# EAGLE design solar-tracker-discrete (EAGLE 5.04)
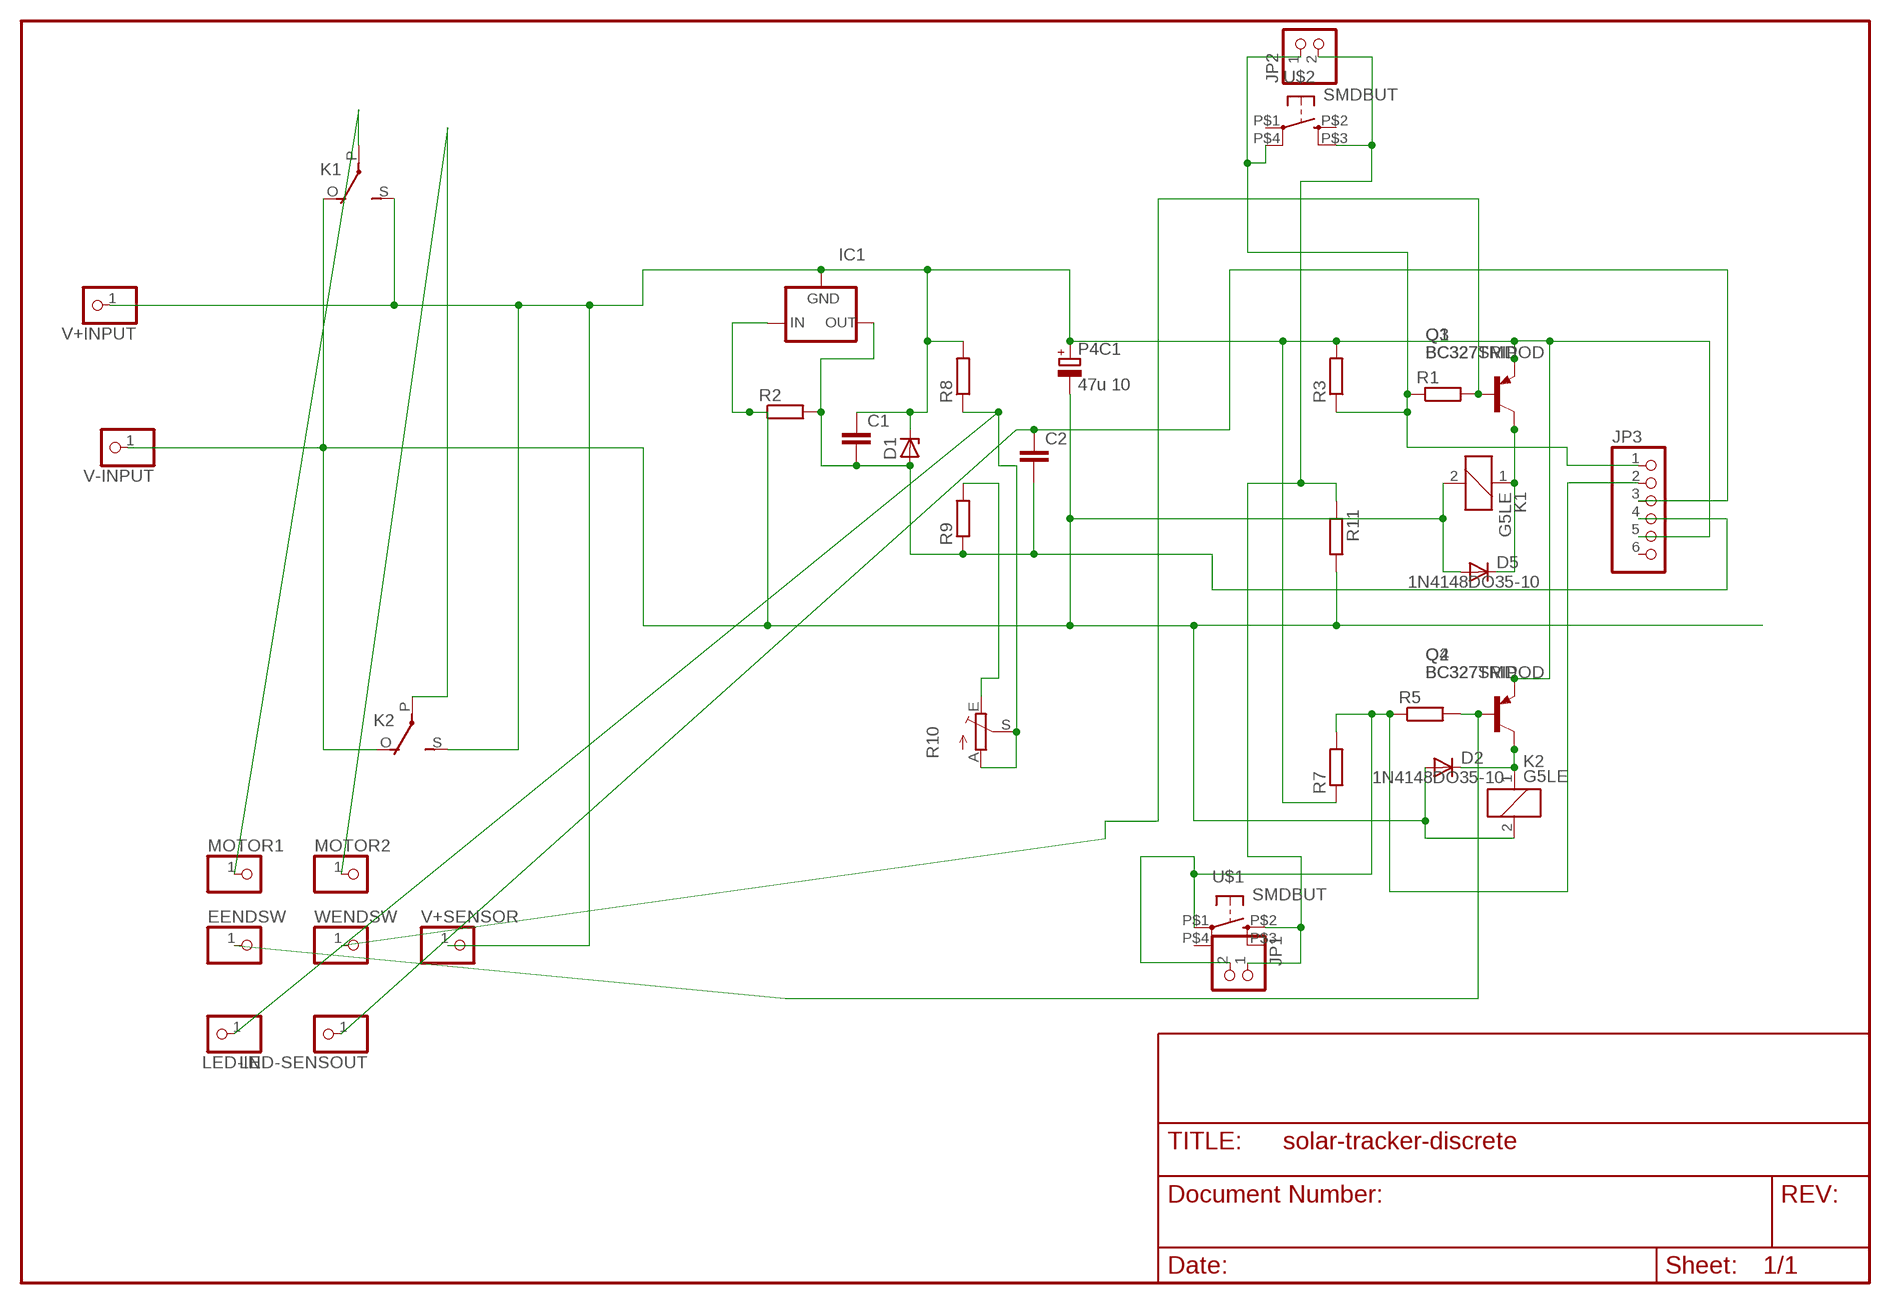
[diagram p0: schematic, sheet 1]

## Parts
C1  C-EUC1206  [C1206]
C2  C-EUC1206  [C1206]
D1  ZENER-DIODESOT23  [SOT23]
D2  1N4148DO35-10  [DO35-10]
D5  1N4148DO35-10  [DO35-10]
EENDSW  PINHD-1X1  [1X01]
IC1  79LXX  [79LXX]
JP1  PINHD-1X2  [1X02]
JP2  PINHD-1X2  [1X02]
JP3  PINHD-1X6  [1X06]
K1  G5LE  [G5LE]
K2  G5LE  [G5LE]
LED-IN  PINHD-1X1  [1X01]
LED-SENSOUT  PINHD-1X1  [1X01]
MOTOR1  PINHD-1X1  [1X01]
MOTOR2  PINHD-1X1  [1X01]
P4C1  47u 10  CPOL-EUE5-8.5  [E5-8,5]
Q1  BC327SMD  [SOT23-BEC]
Q2  BC327SMD  [SOT23-BEC]
Q3  BC327TRIPOD  [TO92]
Q4  BC327TRIPOD  [TO92]
R1  R-EU_0204/2V  [0204V]
R2  R-EU_0204/2V  [0204V]
R3  R-EU_0204/2V  [0204V]
R5  R-EU_0204/2V  [0204V]
R7  R-EU_0204/2V  [0204V]
R8  R-EU_0204/2V  [0204V]
R9  R-EU_0204/2V  [0204V]
R10  TRIM_EU-CA6V  [CA6V]
R11  R-EU_0204/2V  [0204V]
U$1  SMDBUT  [SMD10/5]
U$2  SMDBUT  [SMD10/5]
V+INPUT  PINHD-1X1  [1X01]
V+SENSOR  PINHD-1X1  [1X01]
V-INPUT  PINHD-1X1  [1X01]
WENDSW  PINHD-1X1  [1X01]

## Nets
MOTO1: K2.P(2:P) MOTOR2.1
MOTO2: K1.P(2:P) MOTOR1.1
N$1: R9.2 R10.E
N$3: LED-IN.1 R8.1 R10.A R10.S
N$5: C1.2 C2.2 D1.1(A) IC1.OUT JP3.4 R2.2 R9.1
N$6: JP1.1 JP2.2 R11.1 U$1.P$2(S) U$2.P$3(S1)
N$7: C2.1 JP3.3 LED-SENSOUT.1
N$8: Q1.B Q3.2(B) R1.2 WENDSW.1
N$11: D5.C K1.1 Q1.C Q3.3(C)
N$13: JP2.1 JP3.1 R1.1 R3.1 U$2.P$4(P1)
N$14: JP1.2 JP3.2 R5.1 R7.2 U$1.P$1(P)
N$15: EENDSW.1 Q2.B Q4.2(B) R5.2
Q1-C: D2.C K2.1 Q2.C Q4.3(C)
V+: C1.1 D1.3(C) IC1.GND JP3.5 K1.S(2:S) K2.S(2:S) P4C1.+ Q1.E Q2.E Q3.1(E) Q4.1(E) R3.2 R7.1 R8.2 V+INPUT.1 V+SENSOR.1
V-: D2.A D5.A IC1.IN K1.2 K1.O(2:O) K2.2 K2.O(2:O) P4C1.- R2.1 R11.2 V-INPUT.1
Unconnected: JP3.6 U$1.P$3(S1) U$1.P$4(P1) U$2.P$1(P) U$2.P$2(S)

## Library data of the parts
C1 C2 = rcl-2:C-EU: CAPACITOR, European symbol
D1 = diode-1:ZENER-DIODE: Z-Diode
D2 D5 = diode-1:1N4148: DIODE
EENDSW LED-IN LED-SENSOUT MOTOR1 MOTOR2 V+INPUT V+SENSOR V-INPUT WENDSW = pinhead(2):PINHD-1X1: PIN HEADER
IC1 = v-reg:79LXX: VOLTAGE REGULATOR
JP1 JP2 = pinhead:PINHD-1X2: PIN HEADER
JP3 = pinhead:PINHD-1X6: PIN HEADER
K1 K2 = relay:G5LE: RELAY 1 x switch, 10 A/120 V AC, 8 A/30 V DC, Omron
P4C1 = rcl:CPOL-EU: POLARIZED CAPACITOR, European symbol
Q1 Q2 = transistor-pnp:BC327*: PNP Transistror
Q3 Q4 = transistor-pnp:BC327: PNP Transistor
R1-R3 R5 R7-R9 R11 = rcl-2:R-EU_: RESISTOR, European symbol
R10 = pot:TRIM_EU-: POTENTIOMETER
U$1 U$2 = switch-omron:SMDBUT

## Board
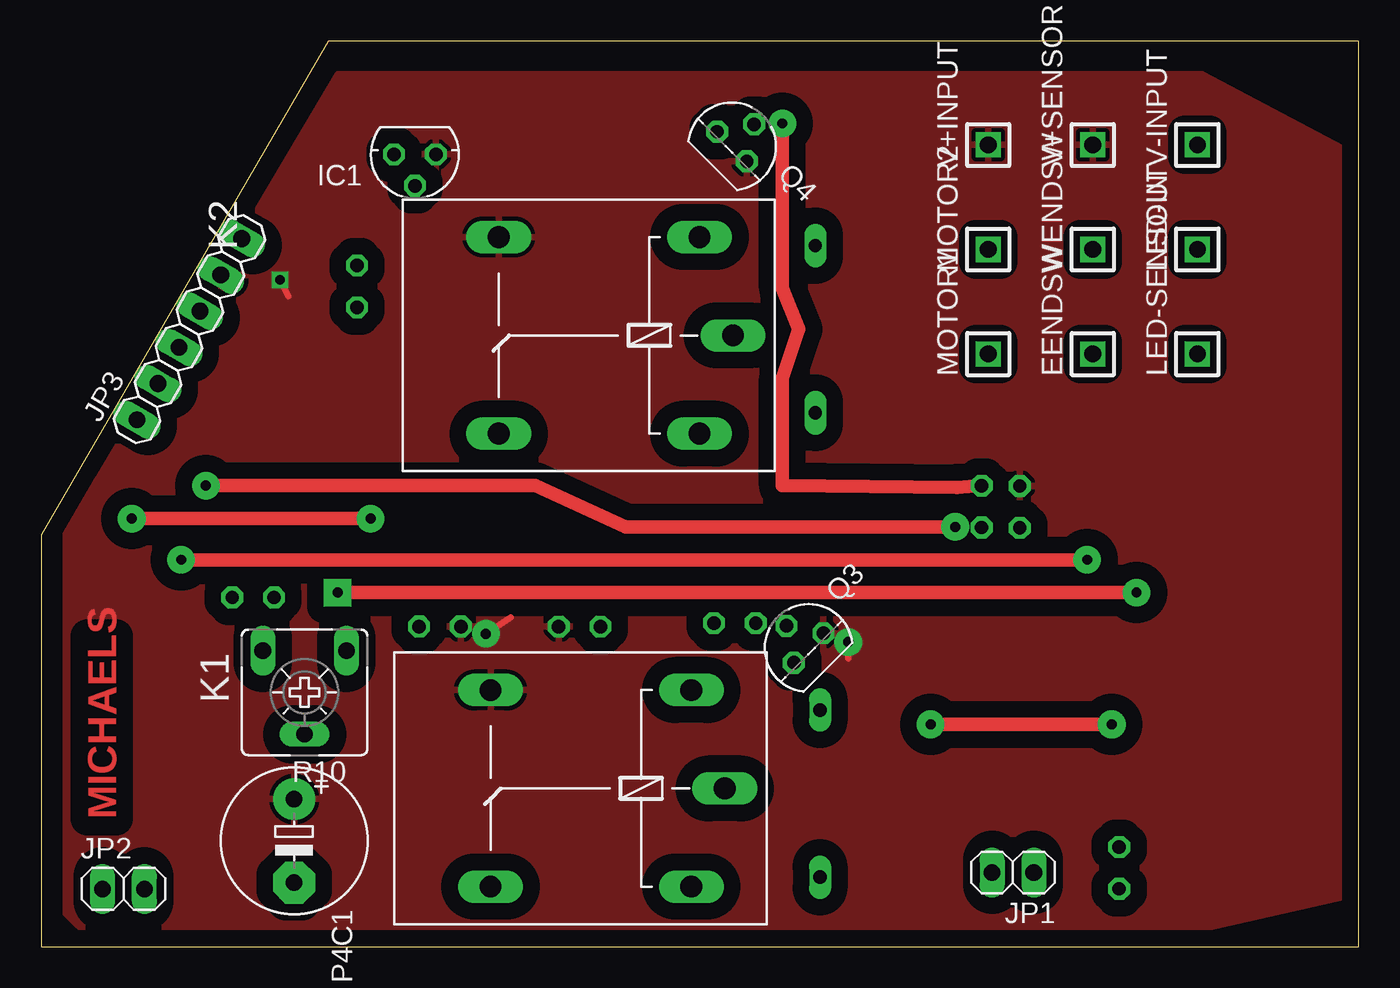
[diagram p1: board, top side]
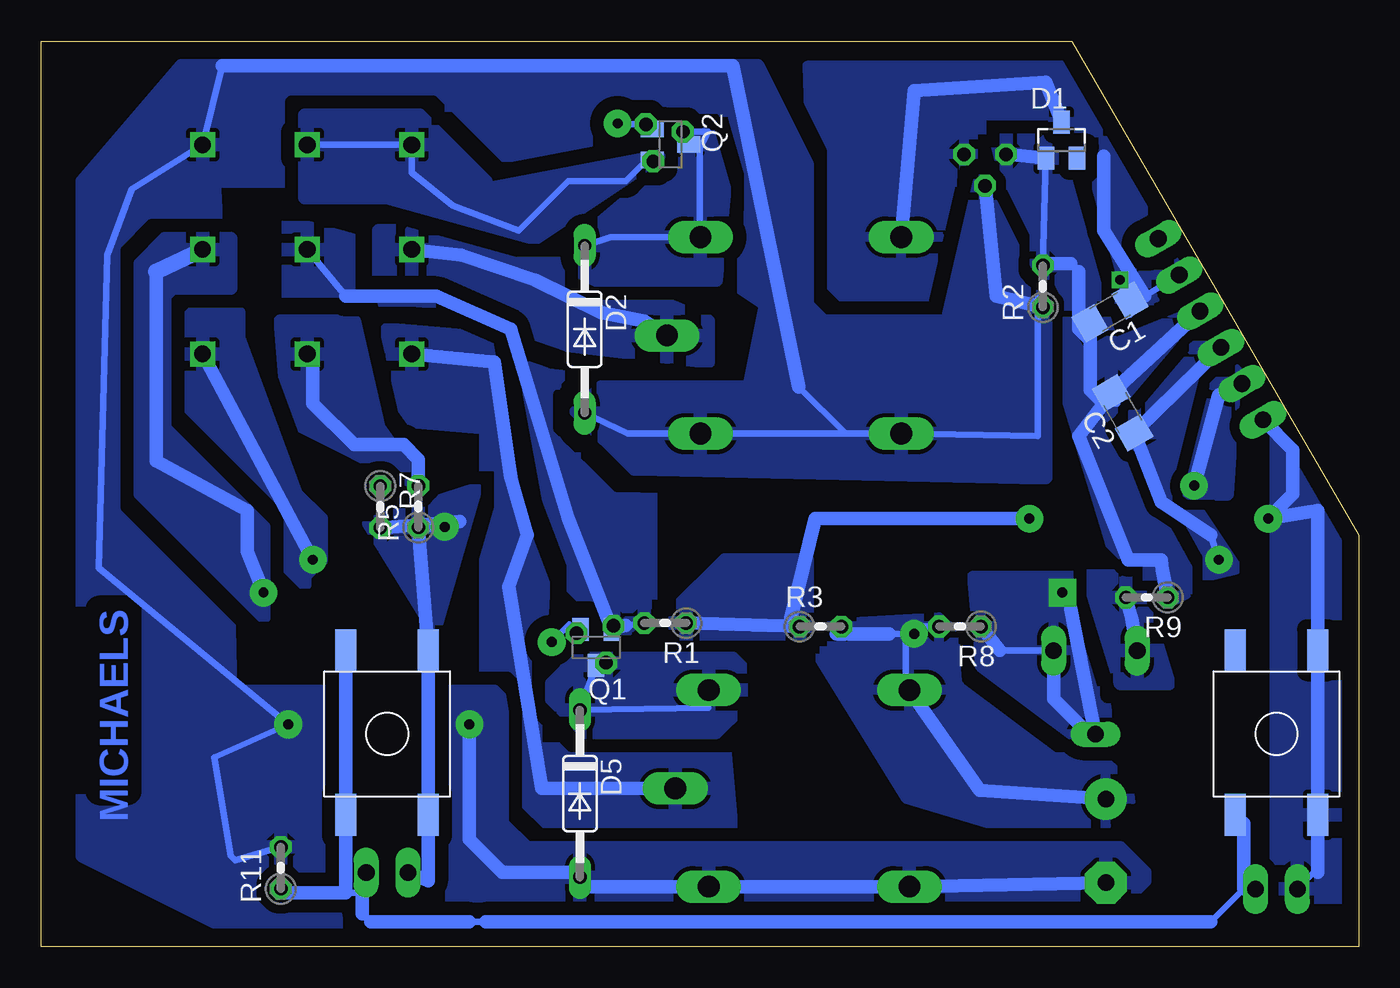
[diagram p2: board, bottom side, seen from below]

Size 80 x 55 mm. Coordinates in mm from the lower left corner, seen from the top.
Outline: 0,0 80,0 80,55 17.43,55 0,25 0,0
Copper layers (1*16): Top 0.035mm / dielectric 1.5mm / Bottom 0.035mm
Design rules "default *": minimum track width 40mil, minimum drill 30mil, track to track 8mil, track to pad 8mil, pad to pad 8mil, via to via 8mil, smd to smd 8mil, copper to edge 40mil, drill to drill 8mil, minimum pad ring 10mil, minimum via ring 8mil, stop-mask expansion 4mil, vias tented up to drill 0mil, thermal gap 10mil

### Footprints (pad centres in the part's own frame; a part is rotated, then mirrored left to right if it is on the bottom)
C1206 = smd 1.6 x 1.8: 1 -1.4,0; 2 1.4,0
SOT23 = smd 1 x 1.4: 1 -0.95,-1.1; 2 0.95,-1.1; 3 0,1.1
DO35-10 = drill 0.813 long: A 5.08,0; C -5.08,0
1X01 = drill 1.016 square: 1 0,0
79LXX = drill 0.813 octagon: GND -1.27,0; IN 0,1.905; OUT 1.27,0
1X02 = drill 1.016 long: 1 -1.27,0; 2 1.27,0
1X06 = drill 1.016 long: 1 -6.35,0; 2 -3.81,0; 3 -1.27,0; 4 1.27,0; 5 3.81,0; 6 6.35,0
G5LE = drill 1.321 long: 1 -7.493,-5.969; 2 -7.493,5.969; O 4.699,5.969; P -9.525,0; S 4.699,-5.969
E5-8,5 = drill 1.016 pad 2.54 round: + -2.54,0 | drill 1.016 pad 2.54 octagon: - 2.54,0
SOT23-BEC = smd 1 x 1.4: B -0.95,-1.1; C 0,1.1; E 0.95,-1.1
TO92 = drill 0.813 octagon: 1 1.27,0; 2 0,1.905; 3 -1.27,0
0204V = drill 0.813 octagon: 1 -1.27,0; 2 1.27,0
CA6V = drill 1.016 long: A -2.54,-2.54; E 2.54,-2.54; S 0,2.54
SMD10/5 = smd 1.27 x 2.54: P$1 -2.5,0; P$2 2.5,0; P$3 2.5,10; P$4 -2.5,10

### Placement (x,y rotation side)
C1  15.1,38.56 210 bottom
C2  14.34,32.42 120 bottom
D1  18.05,48.98 0 bottom
D2  47,37.5 270 bottom
D5  47.29,9.29 270 bottom
EENDSW  63.85,36 90 top
IC1  22.69,48.12 180 top
JP1  59,4.5 180 top
JP2  5,3.5 0 top
JP3  9,37.5 60 top
K1  31.98,9.61 180 top
K2  32.48,37.13 180 top
LED-IN  70.2,42.35 90 top
LED-SENSOUT  70.2,36 90 top
MOTOR1  57.5,36 90 top
MOTOR2  57.5,42.35 90 top
P4C1  15.36,6.42 270 top
Q1  46.31,18.17 180 bottom
Q2  41.79,48.73 270 bottom
Q3  46.6,18.13 45 top
Q4  41.94,48.6 315 top
R1  42.11,19.65 180 bottom
R2  19.18,40.11 90 bottom
R3  32.69,19.44 0 bottom
R5  57.1,26.73 90 bottom
R7  59.41,26.71 270 bottom
R8  24.21,19.44 180 bottom
R9  12.87,21.21 180 bottom
R10  15.99,15.44 180 top
R11  65.45,4.78 90 bottom
U$1  59,18 180 bottom
U$2  5,18 180 bottom
V+INPUT  57.5,48.7 90 top
V+SENSOR  63.85,48.7 90 top
V-INPUT  70.2,48.7 90 top
WENDSW  63.85,42.35 90 top

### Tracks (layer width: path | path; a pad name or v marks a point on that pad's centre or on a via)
MOTO1
  Bottom 0.813: MOTOR2.1 54.5,42 50,40.5 46,38.5 43.38,38 K2.P
  pour Bottom (isolate 0.813, rank 3): 39.5,38 53,43.5 59.5,43.5 59.5,40.5 48,36.5 39.5,35.5
MOTO2
  Bottom 0.813: K1.P 49.61,9.61 51.61,21.89 50.5,25 51.5,28.5 52.5,35.5 MOTOR1.1
  pour Bottom (isolate 0.813, rank 4): 38.5,12 50,12 49.5,22 51,26 53,37 59,37.5 59,32 53,31.5 53,6.5 38,6.5
N$1
  Bottom 0.813: R10.E 13.78,19.93 R9.2
  pour Bottom (isolate 0.61, rank 2): 13.5,22.5 16.5,22.5 14.5,16 11.5,16
N$3  (via drill 0.6 pad 1.68)
  Top 0.813: v18,21.5 v66.5,21.5
  Bottom 0.406: 17.5,20.5 v18,21.5 | 16.5,13 16.09,13 R10.S | R10.A 21.8,17.98
  Bottom 0.813: v66.5,21.5 67.5,24 67.5,26.5 73,29.5 73,41 | R10.S 17.5,20.5 | R10.A 18.54,15.04 16.5,13 | 21.8,17.98 R8.1
  Bottom 1.016: 73,41 LED-IN.1
  pour Bottom (isolate 0.813, rank 3): 15,12.5 16.5,22.5 23.5,22.5 23,17 17,12.5
  pour Bottom (isolate 0.813): 68.5,43 72.5,43 74,41.5 74,27.5 66.5,20 66.5,25.5 67.5,26.5 72.5,31.5 72.5,39.5 72,40 68.5,40
N$5
  Bottom 0.406: D1.1 R2.2 19.5,41.18 19.5,41 19,41.5 | 15.5,33 14.67,33 C2.2 | C1.2 16.31,36.81 | 17,41 17.5,41.5
  Bottom 0.813: C2.2 JP3.4 | R9.1 11.92,22.92 12,23.5 14,23.5 17,31 15.5,33 16.31,33.81 C1.2 | 16.31,36.81 17,37.5 17,41 | 17.5,41.5 19,41.5 | D1.1 IC1.OUT
  pour Bottom (isolate 0.61, rank 3): 10.5,21.5 10.5,23 15.5,32 10,38.5 15,36.5 18.5,49 22,49 20,41 15,24.5 11.5,21
N$6
  Bottom 0.406: JP2.2 7,3.5 9,1.5 | 53,1.5 54,1.5 | 60,1.5 60.5,2 | 60.5,3.27 61.5,3.27 | 65.39,3.27 R11.1 | 7,7.5 U$2.P$3
  Bottom 0.813: 9,1.5 53,1.5 | 54,1.5 60,1.5 | 60.5,2 60.5,3.27 JP1.1 | 65.39,3.27 61.5,3.27 U$1.P$2 | 7,3.5 7,7.5
N$7  (via drill 0.6 pad 1.68)
  Top 0.813: v8.5,23.5 v63.5,23.5
  Bottom 0.406: v8.5,23.5 9,25
  Bottom 0.813: v63.5,23.5 LED-SENSOUT.1 | JP3.3 C2.1 12,27 9,25
  pour Bottom (isolate 0.813, rank 2): 68,38.5 71.5,38.5 72,38 72,30.5 71,29.5 71,29 64,22 64,22.5 63,23.5 63,26 64.5,27.5 68,37
  pour Bottom (isolate 0.61, rank 4): 9.5,37 15.5,32 9.5,22.5 7.5,23 11.5,29
N$8
  Bottom 0.406: 61.5,39.5 WENDSW.1 | 44.5,19.5 R1.2
  Bottom 0.813: 61.5,39.5 56,39.5 51.5,37.5 48,26 Q1.B | Q1.B 44.5,19.5 | Q3.2 Q1.B
  pour Bottom (isolate 1.016, rank 5): 43,20 43,31 52.5,40.5 65,44 65,39 62,39.5 48.5,22.5 45,19
N$11
  Bottom 0.406: Q1.C D5.C 39.5,14.5 K1.1
  Bottom 0.813: Q1.C Q3.3
  pour Bottom (isolate 0.61, rank 2): 37.5,16 37.5,14.5 39,13 47,13 49,15 49,16 47.5,17.5 38,17.5 37.5,17
N$13  (via drill 0.6 pad 1.68)
  Top 0.406: v5.5,26 6,26
  Top 0.813: 6,26 v20,26
  Bottom 0.406: 34.5,19.94 R3.1 | 2.5,4.5 2.73,4.5 JP2.1
  Bottom 0.813: JP3.1 4,30.18 4,27.5 v5.5,26 2.5,26.5 U$2.P$4 2.5,4.5 | R3.1 R1.1 | 34.5,19.94 33,26 v20,26
  pour Bottom (isolate 0.61, rank 3): 5,32.5 0,23.5 0.5,3 5,3
  pour Bottom (isolate 0.61, rank 2): 33.5,23.5 38.5,23.5 41.5,20.5 41.5,19 33.5,19
N$14  (via drill 0.6 pad 1.68)
  Top 0.813: v10,28 30,28 35.5,25.5 v55.5,25.5
  Bottom 0.406: v55.5,25.5 R7.2 | 8.5,33.5 JP3.2
  Bottom 0.813: JP1.2 56.5,4 U$1.P$1 R5.1 54.6,25.82 R7.2 | v10,28 8.5,33.5
  pour Bottom (isolate 0.61): 53.6,27.8 56.1,19.2 60.1,25.7
  pour Bottom (isolate 0.61, rank 5): 7.5,35 10.5,33 10.5,27.5 8,27.5
N$15  (via drill 0.6 pad 1.68)
  Top 0.813: v45,50 45,40 46,37.5 45,34.5 45,28 55.6,27.9 R5.2
  Bottom 0.406: Q4.2 44.95,49.95 v45,50
  Bottom 0.813: R5.2 57.1,29.6 58,30.5 61,30.5 63.5,33 63.5,35.65 EENDSW.1 | Q2.B 43.01,49.67 Q4.2
  pour Bottom (isolate 0.813, rank 3): 61,38 65.5,38 65,32 57,28 59.5,31.5
Q1-C
  Bottom 0.406: 46.69,42.34 D2.C 45.41,43.1 K2.1 40,43.13 40,48.5 39.5,49.5 Q4.3 41.04,49.08 Q2.C
  pour Bottom (isolate 0.813): 39.5,49.5 46,44 47.5,40.5 39,40.5 38.5,46
V+  (via drill 0.6, 0.6 pad 1.68)
  Top 0.406: v49,18.5 49,17.5 | v14.5,40.5 15,39.5 | v27,19 28.5,20
  Bottom 0.406: K1.S 27.5,15.58 27.5,19 28.5,19 v27,19 26.44,19.44 R8.2 | 31.74,19 R3.2 | V+SENSOR.1 V+INPUT.1 57.5,47 55,45 51,43.5 48,46.5 44.5,46.5 43.23,47.77 Q2.E | JP3.5 13,39.5 14,39.5 v14.5,40.5 13.89,38.39 C1.1 | Q1.E 47.93,19.57 v49,18.5
  Bottom 0.813: 28.5,19 31.74,19 | 13,39.5 15.5,43.5 15.5,48 | D1.3 19,52.5 27,52 K2.S | P4C1.+ 23,9.5 K1.S
  pour Top (isolate 1.016, rank 5): 18,53 70.5,53 79,48.5 79,3 68,0.5 3,0.5 1.5,2 1.5,26.5 3.5,28.5
  pour Bottom (isolate 0.61): 50,43 42.5,48 53,46 53,46.5 57,50.5 64,50.5 64,45.5 59,45.5
  pour Bottom (isolate 0.813, rank 4): 14,10 25.5,20 34,19.5 27.5,9 17.5,6 13.5,6
  pour Bottom (isolate 0.813, rank 4): 10,41 16,53.5 33.5,53.5 33,39 25.5,39 15,37.5
V-  (via drill 0.6 pad 1.68)
  Top 0.813: v54,13.5 v65,13.5
  Bottom 0.406: 46.72,3.64 D5.A 47.58,4.5 | K2.O K2.2 44.39,31.16 D2.A | K2.O 31.16,31.16 34,34 | R11.2 68.23,5.23 68.5,5.5 69.5,11.5 v65,13.5 76.5,23 76,42 74.5,46 V-INPUT.1 69,53.5 | K2.O 19.5,31 19.5,39.5 R2.1
  Bottom 0.813: 46.72,3.64 K1.2 K1.O P4C1.- | 34,34 38,53.5 69,53.5 | v54,13.5 54,6.5 52,4.5 47.58,4.5 | IC1.IN 22,39.5 R2.1
  pour Bottom (isolate 0.813, rank 2): 19,38.5 23,46.5 25,38 32.5,38 33.5,39 33.5,47.5 36.5,53.5 71.5,53.5 77.5,46.5 77.5,5.5 69.5,1.5 15.5,1.5 13,4 13,4.5 14.5,6 50.5,6 52,7.5 52,15 52.5,15.5 68.5,15.5 69,37.5 69.5,46.5 42,46.5 37.5,40 36,39 37,34 46,34 47.5,32.5 44,29 20.5,28.5 19,28.5

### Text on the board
Top: MICHAELS
Bottom: MICHAELS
